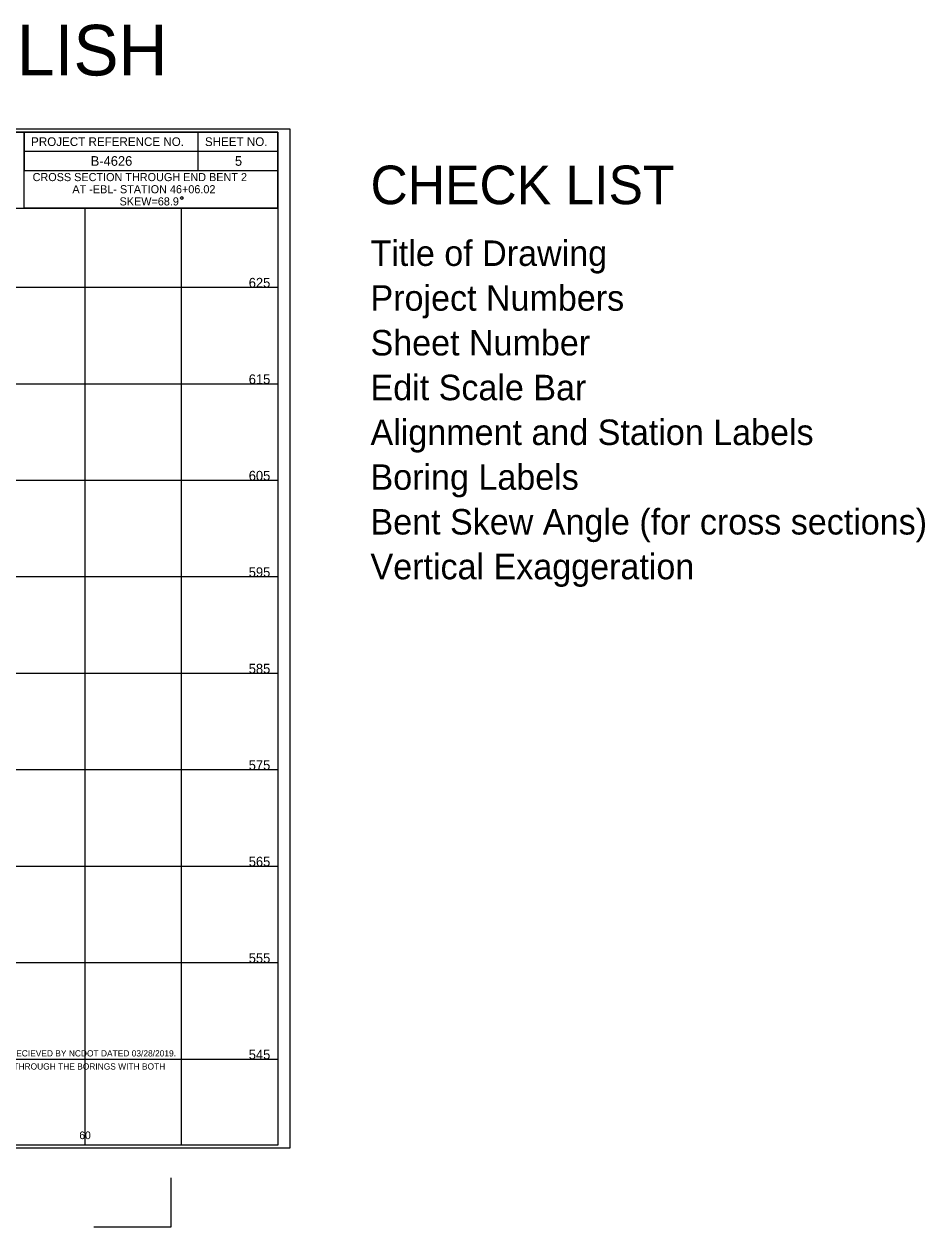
# Model space of a CAD drawing. Extents: x 278618 to 280654, y 171155 to 171855.
# Drawn here: x 280560.4 to 280653.7, y 171180.4 to 171305.1 of the extents above; entities that cross this region are included whole.
import ezdxf

# ---------------------------------------------------------------- set-up
doc = ezdxf.new("R2010")
doc.units = 0
for name, color, linetype in [('Exist Vertical Profile Ground Line', 7, 'Continuous'), ('Geotech Sheets and Borders Cell', 7, 'Continuous'), ('Prop Strc Sect_ Grid - minor', 7, 'Continuous'), ('Scratch_Level_0', 7, 'Continuous'), ('Scratch_Level_2', 7, 'Continuous'), ('Scratch_Level_4', 7, 'Continuous'), ('Sheet Plot Border Inside CELL', 7, 'Continuous')]:
    doc.layers.add(name, color=color, linetype=linetype)

msp = doc.modelspace()

# ---------------------------------------------------------------- linework, layer by layer
at = {"layer": 'Geotech Sheets and Borders Cell'}
for p, q in [((280578.4, 171293.86), (280578.4, 171289.86)), ((280560.39, 171291.86), (280586.69, 171291.86))]:
    msp.add_line(p, q, dxfattribs=at)
for points in [[(280436.69, 171293.86), (280586.69, 171293.86), (280586.69, 171188.86), (280436.69, 171188.86)], [(280534.1, 171285.96), (280586.69, 171285.96), (280586.69, 171293.86), (280534.1, 171293.86)], [(280560.39, 171289.86), (280586.69, 171289.86), (280586.69, 171293.86), (280560.39, 171293.86)], [(280560.39, 171293.86), (280586.69, 171293.86), (280586.69, 171285.96), (280560.39, 171285.96)]]:
    msp.add_lwpolyline(points, close=True, dxfattribs=at)
msp.add_circle((280576.73, 171287.02), 0.141, dxfattribs=at)
at = {"layer": 'Prop Strc Sect_ Grid - minor'}
for p, q in [((280566.69, 171188.86), (280566.69, 171285.96)), ((280576.69, 171188.86), (280576.69, 171285.96)), ((280586.69, 171277.74), (280436.69, 171277.74)), ((280586.69, 171267.74), (280436.69, 171267.74)), ((280586.69, 171257.74), (280436.69, 171257.74)), ((280586.69, 171247.74), (280436.69, 171247.74)), ((280586.69, 171237.74), (280436.69, 171237.74)), ((280586.69, 171227.74), (280436.69, 171227.74)), ((280586.69, 171217.74), (280436.69, 171217.74)), ((280586.69, 171207.74), (280436.69, 171207.74)), ((280586.69, 171197.74), (280436.69, 171197.74))]:
    msp.add_line(p, q, dxfattribs=at)
at = {"layer": 'Scratch_Level_0'}
msp.add_line((280587.94, 171294.14), (280587.94, 171294.14), dxfattribs=at)
at = {"layer": 'Scratch_Level_4'}
msp.add_lwpolyline([(280567.6, 171180.37), (280575.62, 171180.37), (280575.62, 171185.45)], dxfattribs=at)
at = {"layer": 'Sheet Plot Border Inside CELL'}
msp.add_lwpolyline([(280421.17, 171188.58), (280587.94, 171188.58), (280587.94, 171294.14), (280421.17, 171294.14)], close=True, dxfattribs=at)

# ---------------------------------------------------------------- texts
at = {"layer": 'Exist Vertical Profile Ground Line'}
for s, p in [('GROUNDLINE TAKEN FROM .TIN FILE RECIEVED BY NCDOT DATED 03/28/2019.', (280542.99, 171198.04)), ('INFERRED STRATIGRAPHY IS DRAWN THROUGH THE BORINGS WITH BOTH ', (280542.99, 171196.68))]:
    msp.add_text(s, height=0.65, dxfattribs=at).set_placement(p)
at = {"layer": 'Geotech Sheets and Borders Cell'}
for s, height, p in [('PROJECT REFERENCE NO.', 0.9, (280561.1, 171292.41)), ('SHEET NO.', 0.9, (280579.12, 171292.41)), ('B-4626', 1, (280567.28, 171290.36)), ('5', 1, (280582.23, 171290.36)), ('625', 1.001, (280583.66, 171277.74)), ('615', 1.001, (280583.66, 171267.74)), ('605', 1.001, (280583.66, 171257.74)), ('595', 1.001, (280583.66, 171247.74)), ('585', 1.001, (280583.66, 171237.74)), ('575', 1.001, (280583.66, 171227.74)), ('565', 1.001, (280583.66, 171217.74)), ('555', 1.001, (280583.66, 171207.74)), ('545', 1.001, (280583.66, 171197.74)), ('60', 0.8, (280566.1, 171189.47))]:
    msp.add_text(s, height=height, dxfattribs=at).set_placement(p)
for s, p in [('CROSS SECTION THROUGH END BENT 2    ', (280561.26, 171288.77)), ('AT -EBL- STATION 46+06.02 ', (280565.38, 171287.51)), ('SKEW=68.9', (280570.27, 171286.25))]:
    msp.add_text(s, height=0.84, rotation=360, dxfattribs=at).set_placement(p)
at = {"layer": 'Scratch_Level_2'}
msp.add_text('STRUCTURE PROFILE SHEET, ENGLISH', height=5.25, dxfattribs=at).set_placement((280439.88, 171299.72))
at = {"layer": 'Scratch_Level_4'}
for s, height, p in [('CHECK LIST', 4, (280596.28, 171286.38)), ('Title of Drawing', 2.64, (280596.28, 171279.98)), ('Project Numbers', 2.64, (280596.28, 171275.34)), ('Sheet Number', 2.64, (280596.28, 171270.7)), ('Edit Scale Bar', 2.64, (280596.28, 171266.06)), ('Alignment and Station Labels', 2.64, (280596.28, 171261.42)), ('Boring Labels', 2.64, (280596.28, 171256.78)), ('Bent Skew Angle (for cross sections)', 2.64, (280596.28, 171252.14)), ('Vertical Exaggeration', 2.64, (280596.28, 171247.5))]:
    msp.add_text(s, height=height, dxfattribs=at).set_placement(p)

doc.saveas('drawing.dxf')
